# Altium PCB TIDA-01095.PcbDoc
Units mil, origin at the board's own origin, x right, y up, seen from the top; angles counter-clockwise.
Board outline 3070.87 x 3070.87 mil, 2 copper layers (Top Layer, Bottom Layer), stack 62 mil thick; 79 components, 37 nets, 208 pads, 92 vias.
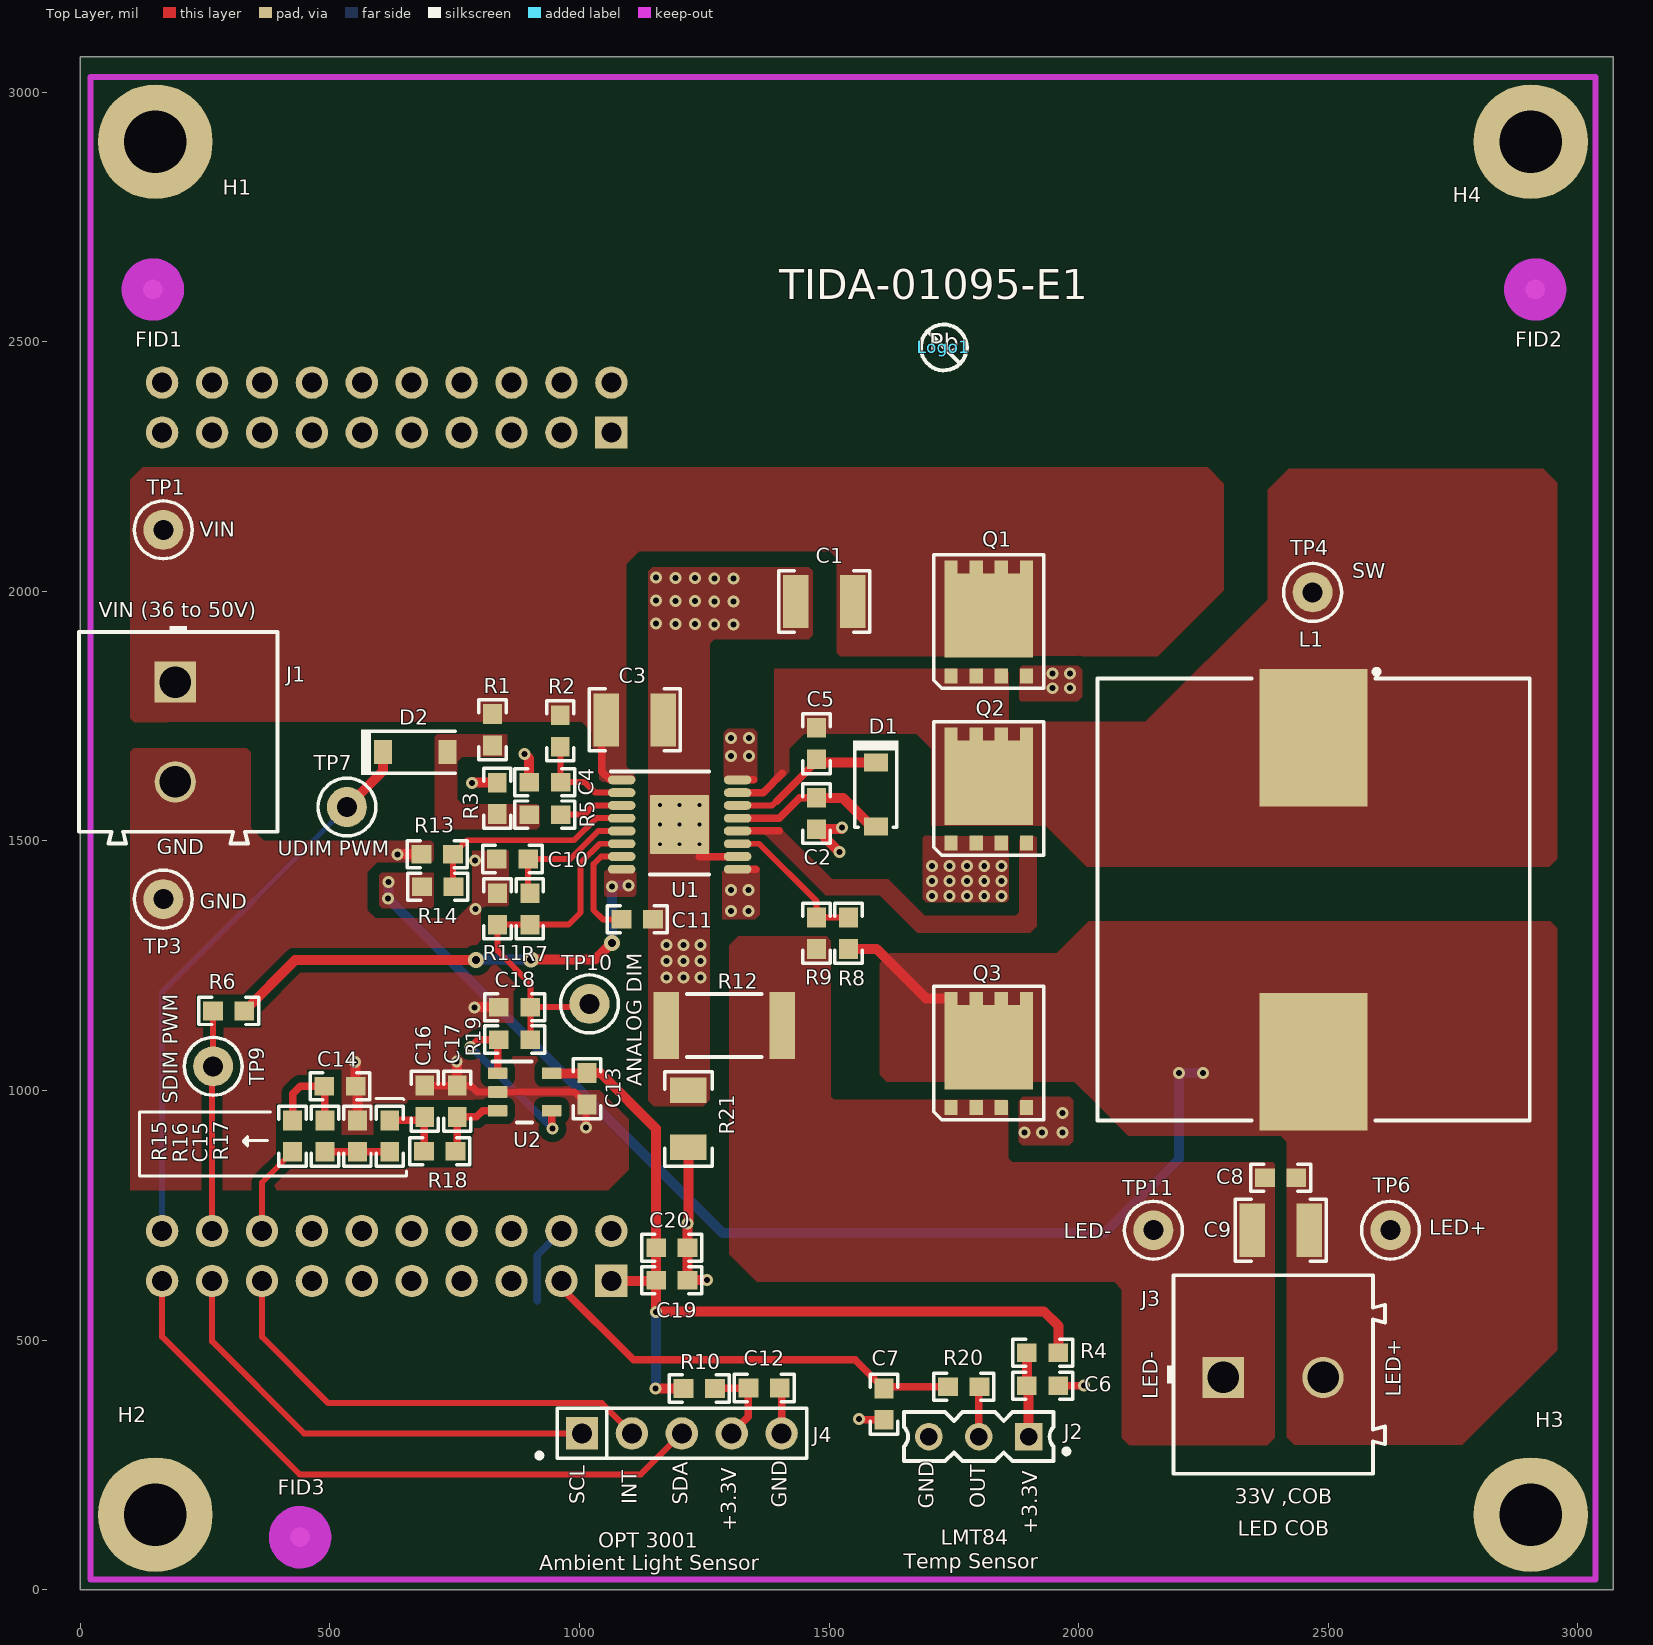
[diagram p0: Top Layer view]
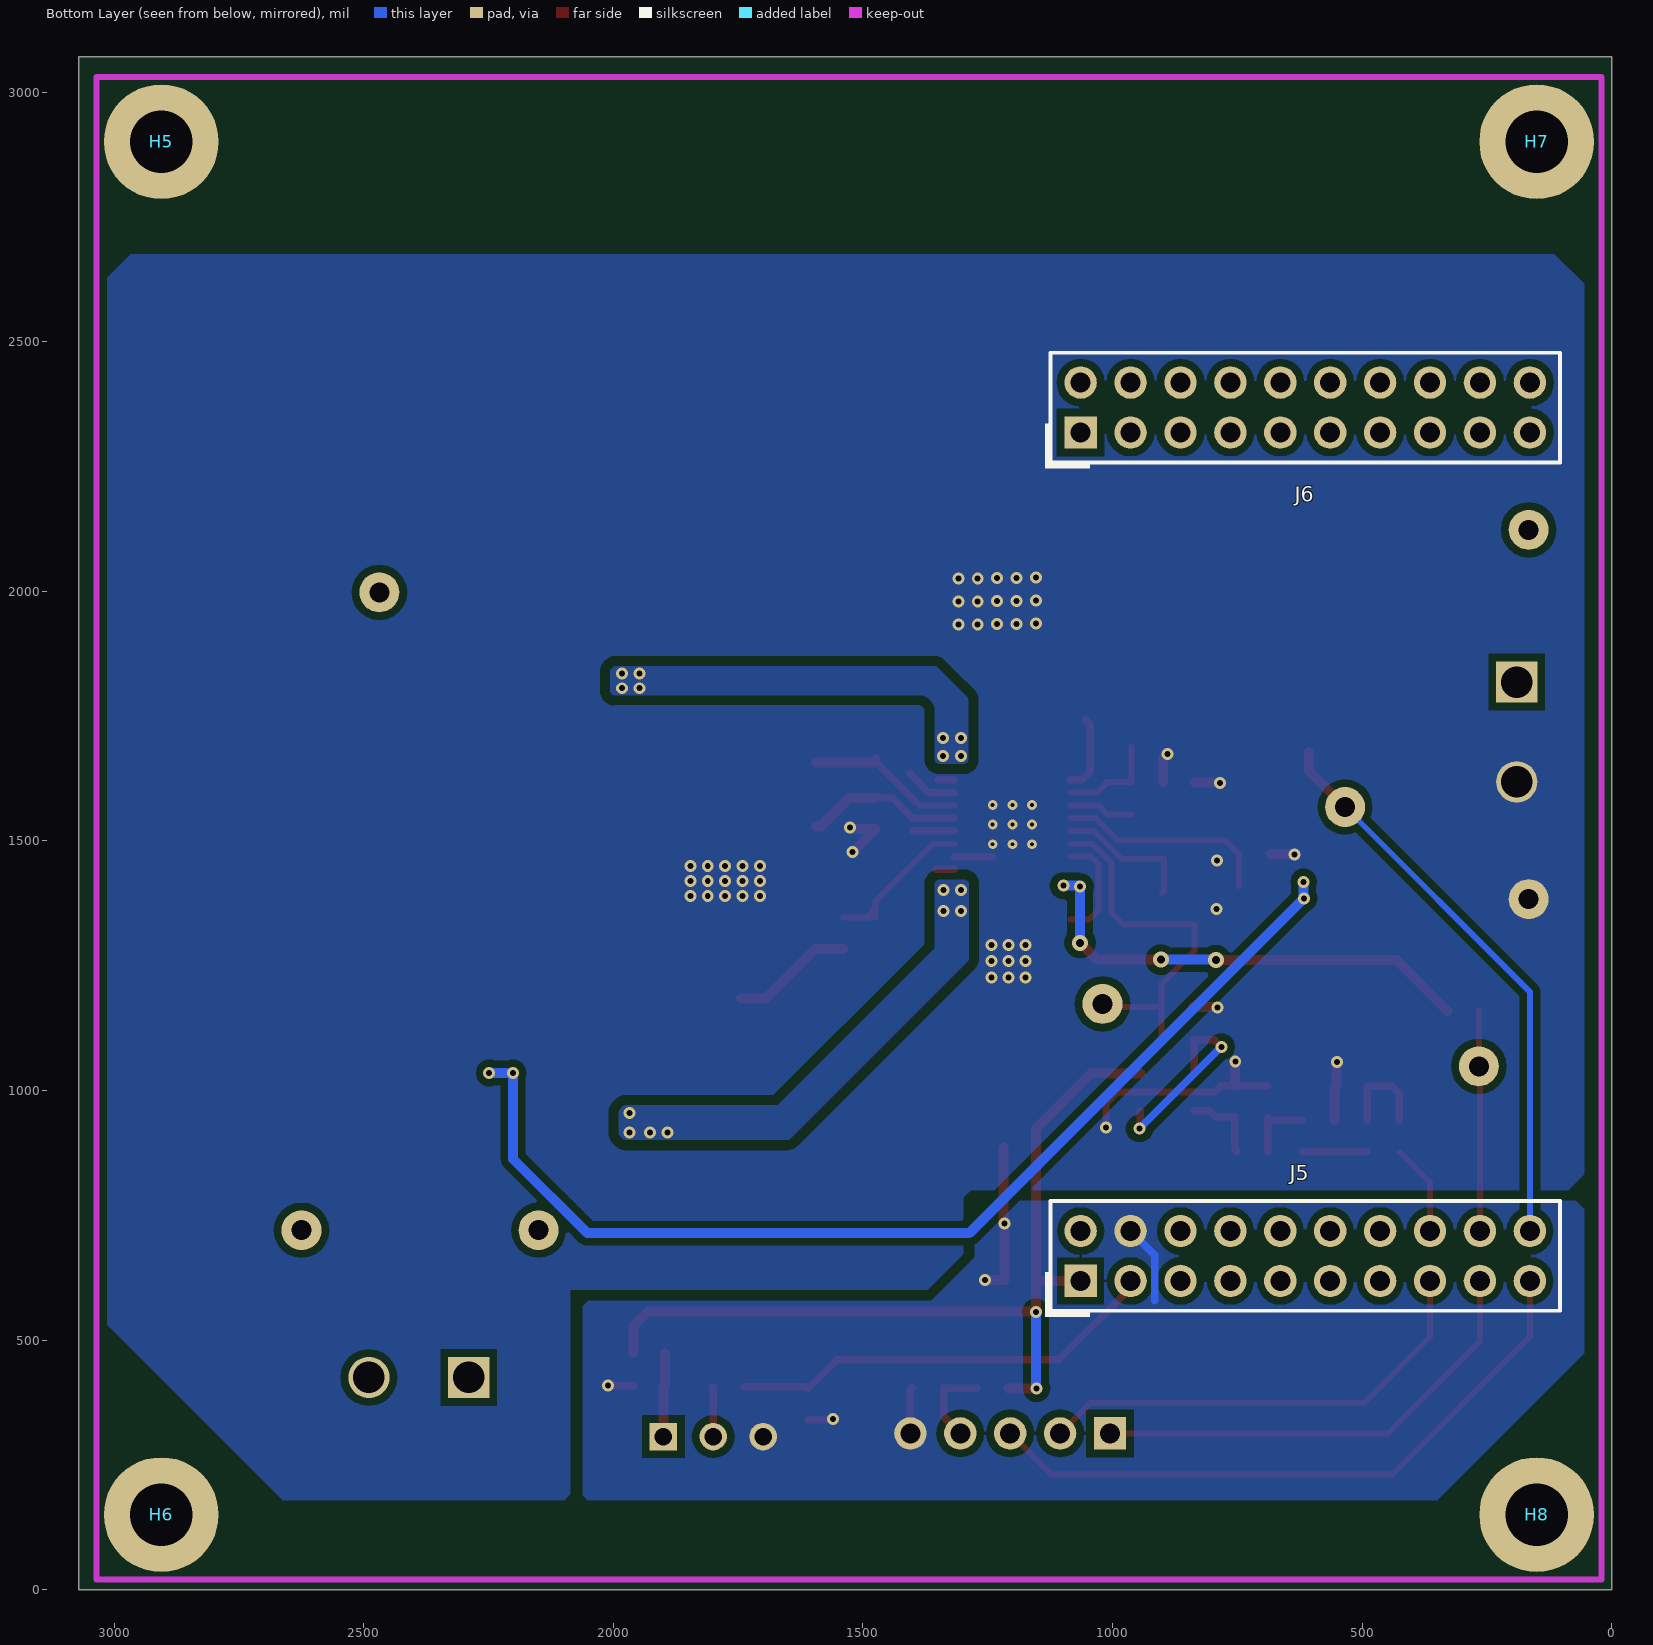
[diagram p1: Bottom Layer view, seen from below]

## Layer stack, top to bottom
Top Solder: solder mask 0.4, Solder Resist, Dk 3.5
Top Layer: signal copper 1.4
Dielectric1: core 59.2, FR-4, Dk 4.8
Bottom Layer: signal copper 1.4
Bottom Solder: solder mask 0.4, Solder Resist, Dk 3.5

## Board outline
0,0 3070.87,0 3070.87,3070.87 0,3070.87

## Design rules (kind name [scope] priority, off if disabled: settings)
AcuteAngle [All] p1: minimum=4.50000000000000E+0001 checktracksonly=FALSE
AssemblyTestPointUsage [All] p1: valid=2
Clearance Clearance_MTG_COPPER [InPadClass('MTG') vs InPoly] p1: gap=40
Clearance "Shape to Shape" [InPolygon vs InPolygon] p2: gap=20
Clearance "shape to all" [InPolygon] p3: gap=15
Clearance Clearance_Boardedge_poly [OnCopper and InPolygon vs IsKeepOut] p4: gap=20
Clearance "Clearance_via_thr pin" [IsVia vs IsThruPin] p5: gap=8
Clearance "SMD to Via" [IsSMTPin vs IsVia] p6: gap=8
Clearance Clearance_u [InPadClass('U1')] p7: gap=7.8
Clearance [All] p8: gap=8
DiffPairsRouting DiffPair_DiffPairsRouting [InDifferentialPair ('kan')] p1: maxlimit=10 minlimit=10 mostfreqgap=10 toplayer_minwidth=15 toplayer_maxwidth=15 toplayer_prefwidth=15 bottomlayer_minwidth=15 bottomlayer_maxwidth=15 bottomlayer_prefwidth=15 maxuncoupledlength=500
DiffPairsRouting DiffPair_DiffPairsRouting_1 [InDifferentialPair ('kan')] p2: maxlimit=10 minlimit=10 mostfreqgap=10 toplayer_minwidth=15 toplayer_maxwidth=15 toplayer_prefwidth=15 bottomlayer_minwidth=15 bottomlayer_maxwidth=15 bottomlayer_prefwidth=15 maxuncoupledlength=500
DiffPairsRouting [All] p3: maxlimit=100 minlimit=10 mostfreqgap=10 toplayer_minwidth=15 toplayer_maxwidth=15 toplayer_prefwidth=15 bottomlayer_minwidth=15 bottomlayer_maxwidth=15 bottomlayer_prefwidth=15 maxuncoupledlength=1000
FabricationTestPointUsage TestPointUsage [All] p1: valid=2 allowmultiple=FALSE
FabricationTestpoint Testpoint [All] p1: side=3 testpointundercomponent=TRUE minsize=40 maxsize=100 preferedsize=60 minholesize=0 maxholesize=40 preferedholesize=32 testpointgrid=1 allowsidetop=TRUE allowsidebottom=TRUE usegrid=TRUE gridtolerance=0.01
FanoutControl Fanout_LCC [IsLCC] p1: bgadir=Out bgaviamode=Centered fanoutstyle=Auto fanoutdirection=Alternating viagrid=1 // Fanout_LCC (Default Rule)
FanoutControl Fanout_BGA [IsBGA] p2: bgadir=Out bgaviamode=Centered fanoutstyle=Auto fanoutdirection=Alternating viagrid=1 // Fanout_BGA (Default Rule)
FanoutControl Fanout_Default [All] p4: bgadir=Out bgaviamode=Centered fanoutstyle=Auto fanoutdirection=Alternating viagrid=1 // Fanout_Default (Default Rule)
FanoutControl Fanout_Small [(CompPinCount < 5)] p5: bgadir=Out bgaviamode=Centered fanoutstyle=Auto fanoutdirection=OutThenIn viagrid=1 // Fanout_Small (Default Rule)
HoleSize [All] p1: absolutevalues=TRUE maxlimit=251 minlimit=7 maxpercent=80.000 minpercent=20.000
MatchedLengths DiffPair_MatchedLengths [InDifferentialPair ('kan')] p1: tolerance=1000 checknetsindiffpair=TRUE checkdiffpairvsdiffpair=FALSE checkothers=FALSE
MatchedLengths DiffPair_MatchedLengths_1 [InDifferentialPair ('kan')] p2: tolerance=1000 checknetsindiffpair=TRUE checkdiffpairvsdiffpair=FALSE checkothers=FALSE
MinimumAnnularRing [All] p1: minimumring=5
MinimumAnnularRing MinimumAnnularRing_ThermalPadVias [IsVia and InAnyComponent] p2: minimumring=5.91
MinimumSolderMaskSliver MinimumSolderMaskSliver_Logo [InComponentClass('Logo') vs InComponentClass('Logo')] p1: minsoldermaskwidth=0.7
MinimumSolderMaskSliver [All] p2: minsoldermaskwidth=3.94
PlaneClearance [All] p1: clearance=15
PlaneConnect [All] p1: planeconnectstyle=Direct reliefexpansion=10 reliefentries=4 reliefconductorwidth=10 reliefairgap=10
PolygonConnect [All] p1: connectstyle=Direct reliefconductorwidth=10 reliefentries=4 polygonreliefangle="90 Angle" airgapwidth=10
RoutingVias RoutingVias_power [InNetClass('POWER')] p1: holewidth=16 width=32 viastyle="Through Hole" minholewidth=7.87 minwidth=19.68 maxholewidth=16 maxwidth=32
RoutingVias ThermalPadVias [IsVia and InAnyComponent] p2: holewidth=8 width=20 viastyle="Through Hole" minholewidth=7.87 minwidth=19 maxholewidth=12 maxwidth=24
RoutingVias [All] p3: holewidth=12 width=24 viastyle="Through Hole" minholewidth=7.87 minwidth=19.68 maxholewidth=16 maxwidth=32
SMDToCorner [All] p1: distance=30000
SilkToSilkClearance [All] p1: silktosilkclearance=5
SilkToSolderMaskClearance SilkscreenOverComponentPads [IsPad] p1: minsilkscreentomaskgap=5 clearancetoexposedcopper=TRUE
SolderMaskExpansion [All] p1: expansion=3
UnpouredPolygon [All] p1: allowunpoured=FALSE
Width Width_power [InNetClass('pwr')] p1: maxlimit=200 minlimit=8 preferedwidth=20
Width [All] p2: maxlimit=100 minlimit=12 preferedwidth=12 checkconnectedcopper=TRUE
15 further rules are at their usual default settings.

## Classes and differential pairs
component class TIDA-01095_Sheet1: C1 C2 C3 C4 C5 C6 C7 C8 C9 C10 C11 C12 C13 C14 C15 C16 C17 C18 C19 C20 D1 D2 J1 J2 J3 J4 J5 J6 L1 Q1 Q2 Q3 R1 R2 R3 R4 R5 R6 R7 R8 R9 R10 R11 R12 R13 R14 R15 R16 R17 R18 R19 R20 R21 TP1 TP3 TP4 TP6 TP7 TP9 TP10 TP11 U1 U2
pad class MTG: H1-1 H2-1 H3-1 H4-1 H5-0 H6-0 H7-0 H8-0
component class Header: J2 J4 J5 J6
component class AssemblyNote: ZZ1 ZZ2 ZZ3 ZZ4
pad class U1: U1-1 U1-2 U1-3 U1-4 U1-5 U1-6 U1-7 U1-8 U1-9 U1-10 U1-11 U1-12 U1-13 U1-14 U1-15 U1-16 U1-17
component class TIDA-01095_Hardware: FID1 FID2 FID3 H1 H2 H3 H4 H5 H6 H7 H8 Logo1 ZZ1 ZZ2 ZZ3 ZZ4
component class FiducialMark: FID1 FID2 FID3

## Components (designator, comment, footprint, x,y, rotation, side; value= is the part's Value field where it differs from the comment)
C1 "GRM32ER72A225KA35L" 1210_270 1490,1980 r180 top
C2 "GRM188R61C225KE15D" 0603 1475,1555 r270 top
C3 "C3225X7R2A105K200AA" 1210 1110.63,1742.8 r0 top
C4 "GRM188R71E182KA01D" 0603 930.63,1617.8 r180 top
C5 "GRM188R71E224KA88D" 0603 1475,1695 r270 top
C6 "GRT188C81A106ME13D" 0603 1928,408.43 r0 top
C7 "GRM188R71E104KA01D" 0603 1610,371.43 r270 top
C8 "GRM188R71E104KA01D" 0603 2405,825 r180 top
C9 "GRM32RR71H105KA01L" 1210_200 2405,720 r180 top
C10 "GRM188R71E104KA01D" 0603 865.63,1463.8 r180 top
C11 "CGA3E3X7R1E474K080AB" 0603 1115.63,1342.8 r0 top
C12 "GRT188C81A106ME13D" 0603 1370,404 r0 top
C13 "GRM188R71E104KA01D" 0603 1015,1003.43 r270 top
C14 "GRM188R70J474KA01D" 0603 520,1008.43 r0 top
C15 "GRM188R70J473KA01D" 0603 555,908.43 r90 top
C16 "GCM188R71H472KA37D" 0603 690,978.43 r90 top
C17 "C0603X471K5RACTU" 0603 755,978.43 r90 top
C18 "GRM188R70J474KA01D" 0603 870,1166.97 r180 top
C19 "GRM188R71E104KA01D" 0603 1185,620 r0 top
C20 "GRT188C81A106ME13D" 0603 1185,685 r180 top
D1 "MBR1H100SFT3G" SOD-123FL 1594,1593 r270 top
D2 "1N4148W-7-F" SOD-123 670.63,1677.8 r0 top
FID1 "Fiducial" Fiducial10-30 145,2605 r0 top
FID2 "Fiducial" Fiducial10-30 2915,2605 r90 top
FID3 "Fiducial" Fiducial10-30 440,105 r90 top
H1 "PMSSS 440 0025 PH" B_F_PMSSS4400025PH 150,2901 r0 top
H2 "PMSSS 440 0025 PH" B_F_PMSSS4400025PH 150,150 r0 top
H3 "PMSSS 440 0025 PH" B_F_PMSSS4400025PH 2906,150 r0 top
H4 "PMSSS 440 0025 PH" B_F_PMSSS4400025PH 2906,2901 r0 top
H5 "1902E" Keystone_1902E 2906,2901 r180 bottom
H6 "1902E" Keystone_1902E 2906,150 r180 bottom
H7 "1902E" Keystone_1902E 150,2901 r180 bottom
H8 "1902E" Keystone_1902E 150,150 r180 bottom
J1 "691216510002" Wurth_691216510002 190,1718.43 r270 top
J2 "SL 11 112 03G" Fischer_SL-11-112-03G 1800,306.43 r180 top
J3 "691216510002" Wurth_691216510002 2390,425 r0 top
J4 "TSW-105-07-G-S" TSW-105-07-G-S 1205,313 r0 top
J5 "PEC10DAAN" SULLINS_PEC10DAAN 613.75,668.43 r90 bottom locked
J6 "PEC10DAAN" SULLINS_PEC10DAAN 613.75,2368.43 r90 bottom locked
L1 "68.0 μH" "WE-HCI 2212" 2471,1382.43 r0 top
Logo1 "Pb-Free Symbol" Pb-Free_Overlay_Small 1730,2489 r0 top
Q1 "CSD18537NQ5A" TRANS_NexFET_Q5A 1820,1940 r90 top
Q2 "CSD18563Q5A" TRANS_NexFET_Q5A 1820,1605 r90 top
Q3 "CSD18563Q5A" TRANS_NexFET_Q5A 1820,1075 r90 top
R1 "CRCW0603120KJNEA" 0603 825.63,1722.8 r90 top
R2 "CRCW060347K0JNEA" 0603 961.65,1720.6 r90 top
R3 "CRCW06034K99FKEA" 0603 835,1585.43 r270 top
R4 "RC0603FR-07100RL" 0603 1928,474.43 r0 top
R5 "CRCW060320K0FKEA" 0603 930.63,1552.8 r0 top
R6 "RC0603FR-07866RL" 0603 297,1159.43 r0 top
R7 "CRCW060310K0FKEA" 0603 900.63,1363.8 r90 top
R8 "CRCW06031M21FKEA" 0603 1539,1315 r270 top
R9 "CRCW0603475RFKEA" 0603 1475,1315 r270 top
R10 "RC0603FR-07100RL" 0603 1240,403 r0 top
R11 "CRCW060310K0FKEA" 0603 835.63,1363.8 r270 top
R12 "CSRN2512FK50L0" 2512 1290,1130 r0 top
R13 "CRCW06035K60JNEA" 0603 715,1473.43 r0 top
R14 "RC0603FR-07100KL" 0603 716,1408 r180 top
R15 "RC0603FR-07866RL" 0603 425,908.43 r90 top
R16 "RC0603FR-078K66L" 0603 490,908.43 r270 top
R17 "CRCW060386K6FKEA" 0603 620,908.43 r90 top
R18 "RC0603FR-07866KL" 0603 720,878.43 r0 top
R19 "CRCW060311K0FKEA" 0603 870,1101.97 r0 top
R20 "RC0603FR-071K5L" 0603 1770,406.43 r0 top
R21 "MCR18EZHJ000" 1206 1218,943 r90 top
TP1 "5002" Keystone5002 166,2123.43 r180 top
TP3 "5002" Keystone5002 166,1383.43 r0 top
TP4 "5002" Keystone5002 2469,1998 r0 top
TP6 "5002" Keystone5002 2625,720 r0 top
TP7 "5002" Keystone5002 534,1568 r90 top
TP9 "5002" Keystone5002 266,1048.43 r0 top
TP10 "5002" Keystone5002 1020,1173.43 r180 top
TP11 "5002" Keystone5002 2150,720 r0 top
U1 "TPS92641PWPR/NOPB" PWP0016A_N 1200.63,1532.8 r0 top
U2 "OPA376AIDBVR" DBV0005A_N 890,996.97 r0 top
ZZ1 "This Assembly Note is for PCB labels only" AssemblyNoteLabel 210.18,6697.51 r0 top
ZZ2 "These assemblies are ESD sensitive, ESD precautions shall be observed." AssemblyNote 1561.9,9244.61 r0 top
ZZ3 "These assemblies must be clean and free from flux and all contaminants. Use of no clean flux is not acceptable." AssemblyNote 1561.9,9159.61 r0 top
ZZ4 "These assemblies must comply with workmanship standards IPC-A-610 Class 2, unless otherwise specified." AssemblyNote 1561.9,9084.61 r0 top

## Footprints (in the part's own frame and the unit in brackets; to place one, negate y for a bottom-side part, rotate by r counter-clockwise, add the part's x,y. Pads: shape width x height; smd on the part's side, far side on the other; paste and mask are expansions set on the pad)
0603 [mm] "0603 from SM-752 data"
  rect 1x0.95 smd: 1(-0.8,0) 2(0.8,0)
  silkscreen extent -1.52,-0.69 1.52,0.69, body extent -0.87,-0.47 0.87,0.47, height 1
1206 [mm] "1206 from SM-752 data"
  rect 1.3x1.85 smd: 1(-1.45,0) 2(1.45,0)
  silkscreen extent -2.4,-1.21 2.4,1.21, body extent -1.7,-0.9 1.7,0.9, height 1.35
1210 [mm] "1210 from SM-752 data"
  rect 1.3x2.7 smd: 1(-1.45,0) 2(1.45,0)
  silkscreen extent -2.32,-1.57 2.32,1.57, body extent -1.7,-1.35 1.7,1.35, height 1.35
1210_200 [mm] "1210"
  rect 1.3x2.7 smd: 1(-1.45,0) 2(1.45,0)
  silkscreen extent -2.32,-1.57 2.32,1.57, body extent -1.7,-1.35 1.7,1.35, height 2
1210_270 [mm] "1210"
  rect 1.3x2.7 smd: 1(-1.45,0) 2(1.45,0)
  silkscreen extent -2.32,-1.57 2.32,1.57, body extent -1.7,-1.35 1.7,1.35, height 2.7
2512 [mm] "Chip Resistor, Body 6.3x3.2mm, IPC Medium Density"
  rect 1.3x3.4 smd: 1(-2.95,0) 2(2.95,0)
  silkscreen extent -1.9,-1.6 1.9,1.6, body extent -3.22,-1.67 3.22,1.67, height 0.71
AssemblyNote [mil] "Assembly Note"
AssemblyNoteLabel [mil] "Assembly Note for PCB Labels"
B_F_PMSSS4400025PH [mil] "MACHINE SCREW PAN PHILLIPS 4-40"
  round 230 hole 125: 1(0,0)
  body extent -109,-109 110,110, height 79
DBV0005A_N [mm] "SOT23, 5-Leads, Body 2.9x1.6mm, Pitch 0.95mm, Lead Span 2.8mm, IPC Medium Density"
  rrect17% 1x0.6 smd: 1(-1.375,0.95) 2(-1.375,0) 3(-1.375,-0.95) 4(1.375,-0.95) 5(1.375,0.95)
  silkscreen extent -1.63,-1.55 0.38,1.55, body extent -1.42,-1.46 1.42,1.46, height 1.09
Fiducial10-30 [mm]
  round 1 smd mask+1: 1(0,0)
  Top Layer keep-out circle w1.678: c0,0 r0.75
Fischer_SL-11-112-03G [mm] "TH, 3-Leads, Body 2.5x7.62mm, Pitch 2.54mm"
  rect 1.4x1.4 hole 0.9: 1(-2.54,0)
  round 1.4 hole 0.9: 2(0,0) 3(2.54,0)
  silkscreen extent -4.59,-1.25 3.81,1.25, body extent -3.81,-1.25 3.81,1.25, height 8.4
Keystone5002 [mil] "For Keystone 500x miniature loop terminals"
  round 80 hole 40: 1(0,0)
  silkscreen extent -58,-58 58,58, body extent -49,-49 49,49, height 182
Keystone_1902E [mil] "Hex Standoff, 4-40 threaded, nylon"
  round 1 on Mech4: 0(0,0)
  body extent -145,-126 146,126, height 1001
Pb-Free_Overlay_Small [mil]
  silkscreen extent -46,-46 46,46
PWP0016A_N [mm] "TSOP, 16-Leads, Body 5x4.4mm, Pitch 0.65mm, Exposed Pad, IPC Medium Density"
  rrect100% 1.4x0.45 smd: 1(-2.95,2.275) 2(-2.95,1.625) 3(-2.95,0.975) 4(-2.95,0.325) 5(-2.95,-0.325) 6(-2.95,-0.975) 7(-2.95,-1.625) 8(-2.95,-2.275) 9(2.95,-2.275) 10(2.95,-1.625) 11(2.95,-0.975) 12(2.95,-0.325) 13(2.95,0.325) 14(2.95,0.975) 15(2.95,1.625) 16(2.95,2.275)
  rrect3% 3x3 smd: 17(0,0)
  silkscreen extent -3.5,-2.55 1.5,2.7, body extent -3.21,-2.5 3.21,2.5, height 1
SOD-123 [mm] "On Semi recommended land pattern"
  rect 0.915x1.22 smd: 1(-1.637,0) 2(1.637,0)
  silkscreen extent -2.74,-1.17 2.03,1.17, body extent -1.93,-0.9 1.93,0.9, height 1.35
SOD-123FL [mm] "Copied from SOD-123"
  rect 0.915x1.22 smd: 1(-1.637,0) 2(1.637,0)
  silkscreen extent -2.74,-1.16 1.68,1.16, body extent -1.9,-0.9 1.9,0.9, height 1
SULLINS_PEC10DAAN [mm] "SULLINS"
  rect 1.65x1.65 hole 1.016: 1(-1.27,11.43)
  round 1.65 hole 1.016: 2(1.27,11.43) 3(-1.27,8.89) 4(1.27,8.89) 5(-1.27,6.35) 6(1.27,6.35) 7(-1.27,3.81) 8(1.27,3.81) 9(-1.27,1.27) 10(1.27,1.27) 11(-1.27,-1.27) 12(1.27,-1.27) 13(-1.27,-3.81) 14(1.27,-3.81) 15(-1.27,-6.35) 16(1.27,-6.35) 17(-1.27,-8.89) 18(1.27,-8.89) 19(-1.27,-11.43) 20(1.27,-11.43)
  silkscreen extent -3.11,-12.96 2.79,13.25, body extent -2.79,-12.96 2.79,12.96, height 9.08
TRANS_NexFET_Q5A [mm] "TI recommended land pattern (nominal) M0139-01"
  rect 0.75x0.675 smd paste-0.1 mask+0.051: 1(-2.776,1.917) 2(-2.776,0.639) 3(-2.776,-0.639) 4(-2.776,-1.917)
  rect 0.655x0.675 smd paste-0.1 mask+0.051: 5(2.776,-1.917) 6(2.776,-0.639) 7(2.776,0.639) 8(2.776,1.917)
  rect 4.295x4.51 smd paste-2.2 mask+0.051: 9(0.301,0)
  silkscreen extent -3.4,-2.8 3.4,2.8, body extent -3.05,-2.5 3.05,2.5, height 1.11
TSW-105-07-G-S [mm] "Samtec 100mil, 1x5, 230 mil above insulator"
  rect 1.65x1.65 hole 1.016 mask+0: 1(-5.08,0)
  round 1.65 hole 1.016 mask+0.076: 2(-2.54,0) 3(0,0) 4(2.54,0) 5(5.08,0)
  silkscreen extent -7.37,-1.27 6.35,1.27, body extent -6.35,-1.27 6.35,1.27, height 8.38
"WE-HCI 2212" [mm] "High Current Inductor, 2-Leads, Body 22.0x22.5mm"
  rect 5.5x7 smd: 1(0,8.25) 2(0,-8.25)
  silkscreen extent -11,-11.25 11,11.72, body extent -11,-11.25 11,11.25, height 12
Wurth_691216510002 [mm] "Receptacle, 5.08mm, 2x1, TH"
  rect 2.1x2.1 hole 1.6: 1(-2.54,0)
  round 2.1 hole 1.6: 2(2.54,0)
  silkscreen extent -5.4,-4.9 5.68,5.2, body extent -5.1,-4.9 5.66,5.2, height 13.8

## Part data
C1: "CAP, CERM, 2.2 µF, 100 V, +/- 10%, X7R, 1210"
C2: "CAP, CERM, 2.2 µF, 16 V, +/- 10%, X5R, 0603"
C3: "CAP, CERM, 1 µF, 100 V, +/- 10%, X7R, 1210"
C4: "CAP, CERM, 1800 pF, 25 V, +/- 10%, X7R, 0603"
C5: "CAP, CERM, 0.22 µF, 25 V, +/- 10%, X7R, 0603"
C6 C12 C20: "CAP, CERM, 10 µF, 10 V, +/- 20%, X6S, AEC-Q200 Grade 2, 0603"
C7 C8 C10 C13 C19: "CAP, CERM, 0.1 µF, 25 V, +/- 10%, X7R, 0603"
C9: "CAP, CERM, 1 µF, 50 V, +/- 10%, X7R, 1210"
C11: "CAP, CERM, 0.47 µF, 25 V, +/- 10%, X7R, AEC-Q200 Grade 1, 0603"
C14 C18: "CAP, CERM, 0.47 µF, 6.3 V, +/- 10%, X7R, 0603"
C15: "CAP, CERM, 0.047 µF, 6.3 V, +/- 10%, X7R, 0603"
C16: "CAP, CERM, 4700 pF, 50 V, +/- 10%, X7R, AEC-Q200 Grade 1, 0603"
C17: "CAP, CERM, 470 pF, 50 V, +/- 10%, X7R, 0603"
D1: "Diode, Schottky, 100 V, 1 A, SOD-123FL"
D2: "Diode, Ultrafast, 100 V, 0.15 A, SOD-123"
FID1 FID2 FID3: "Fiducial mark.  There is nothing to buy or mount."
H1 H2 H3 H4: "MACHINE SCREW PAN PHILLIPS 4-40"
H5 H6 H7 H8: "Standoff, Hex, 1\"L #4-40 Nylon"
J1 J3: "Receptacle, 5.08mm, 2x1, Brass, TH"
J2: "Header, 2.54mm, 3x1, Gold, TH"
J4: "Header, 100mil, 5x1, Gold, TH"
J5 J6: "Header, 100mil, 10x2, TH"
L1: library part "WE-HCI 2212, 74435586800", "WE-HCI SMD Flat Wire High Current Inductor, Inductance = 68.0 µH"
Logo1: library part Pb-Free
Q1: "MOSFET, N-CH, 60 V, 50 A, SON 5x6mm"
Q2 Q3: "MOSFET, N-CH, 60 V, 15 A, SON 5x6mm"
R1: "RES, 120 k, 5%, 0.1 W, 0603"
R2: "RES, 47 k, 5%, 0.1 W, 0603"
R3: "RES, 4.99 k, 1%, 0.1 W, 0603"
R4 R10: "RES, 100, 1%, 0.1 W, 0603"
R5: "RES, 20.0 k, 1%, 0.1 W, 0603"
R6 R15: "RES, 866, 1%, 0.1 W, 0603"
R7 R11: "RES, 10.0 k, 1%, 0.1 W, 0603"
R8: "RES, 1.21 M, 1%, 0.1 W, 0603"
R9: "RES, 475, 1%, 0.1 W, 0603"
R12: "RES, 0.05, 1%, 2 W, 2512"
R13: "RES, 5.6 k, 5%, 0.1 W, 0603"
R14: "RES, 100 k, 1%, 0.1 W, 0603"
R16: "RES, 8.66 k, 1%, 0.1 W, 0603"
R17: "RES, 86.6 k, 1%, 0.1 W, 0603"
R18: "RES, 866 k, 1%, 0.1 W, 0603"
R19: "RES, 11.0 k, 1%, 0.1 W, 0603"
R20: "RES, 1.50 k, 1%, 0.1 W, 0603"
R21: "RES, 0, 5%, 0.25 W, 1206"
TP1 TP3 TP4 TP6 TP7 TP9 TP10 TP11: "Test Point, Miniature, White, TH"
U1: "Synchronous Buck Controller for Precision Dimming LED Drivers, PWP0016A"
U2: "Precision, Low Noise, Low Iq Operational Amplifier, 2.2 to 5.5 V, -40 to 125 degC, 5-pin SOT23 (DBV0005A), Green (RoHS & no Sb/Br)"
ZZ1: library part AssemblyNoteLabel
ZZ2 ZZ3 ZZ4: library part AssemblyNote

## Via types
v1: diameter 24, hole 12, Top Layer to Bottom Layer, tented both sides, 80 vias
v2: diameter 19.68, hole 7.87, Top Layer to Bottom Layer, tented both sides, 9 vias
v3: diameter 32, hole 16, Top Layer to Bottom Layer, tented both sides, 3 vias

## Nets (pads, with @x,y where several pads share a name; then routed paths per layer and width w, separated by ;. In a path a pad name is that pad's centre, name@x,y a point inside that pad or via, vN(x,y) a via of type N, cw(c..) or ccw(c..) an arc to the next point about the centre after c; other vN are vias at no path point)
+3.3V: C13.1 C19.1 C20.2 J5.1 R4.2 R10.1 U2.5 | length 1795.2
  Top Layer w20: U2.5 1014.45,1034.37 C13.1 1042.08,1034.92 1153.5,923.5 C19.1 ; J5.1 1151.93,618.43 C19.1 ; v1(1152,403) R10.1 ; v1(1153.5,556.5) C19.1 ; v1@1154.01,557 1931,557 1959.5,528.5 R4.2
  Bottom Layer w20: v1(1152,403) 1153.5,404.5 v1(1153.5,556.5)
+5V: J5.2
DIO0: J5.18 R6.1 TP9.1 | length 442.1
  Top Layer w12: J5.18 263.75,1046.17 TP9.1 266,1158.93 R6.1
DIO1: D2.1 J5.20 TP7.1 | length 1142.6
  Top Layer w20: TP7.1 606.16,1640.16 D2.1
  Bottom Layer w12: J5.20 163.75,1197.75 TP7.1
DIO4_SCL: J4.1 J5.17 | length 938.7
  Top Layer w12: J5.17 263.75,497.25 448,313 J4.1
DIO5_SDA: J4.3 J5.19 | length 1301.4
  Top Layer w12: J5.19 163.75,506.25 439,231 1123,231 J4.3
DIO21: J4.2 J5.15 | length 933.5
  Top Layer w12: J5.15 363.75,506.25 496.57,373.43 1044.57,373.43 J4.2
DIO30: J5.16 R15.1 | length 183.9
  Top Layer w12: J5.16 363.75,815.68 R15.1
GND: C1.2 C2.2 C3.2 C4.2 C10.2 C11.2 C13.2 C14.2 C15.2 C16.2 C17.2 C18.2 J1.2 Q2.1 Q2.2 Q2.3 R3.1 R11.1 R12.1 R13.1 R21.2 TP3.1 U1.10 U1.17 U2.2 | length 956.5
  Top Layer w15: C16.2 C17.2 782.05,1009.92 795,996.97 U2.2 989.96,996.97 C13.2 1013,969.93 v1(1013,925.43) ; 1240.4,1468.82 U1.10
  Top Layer w20: v1(550.5,1056.93) 551.5,1055.93 C14.2 555,1004.92 C15.2 ; v1(635,1472.43) 636,1473.43 R13.1 ; v1(754,1058.43) 755,1057.42 C17.2 ; v1(785.01,1616.43) 785.5,1616.92 R3.1 ; v1(790,1165.97) 791,1166.97 C18.2 ; v1(890,1674.43) 899.14,1665.29 C4.2 ; v1(1521,1478) 1520.5,1478 C2.2 v1@1522.5,1523.5 ; v1@1526,1523.5 v1(1526,1527)
  other v1: 1174,1226 1208,1226 1242,1226 1174,1259 1208,1259 1242,1259 1174,1292 1208,1292 1242,1292 792,1364 1706,1390 1741,1390 1776,1390 1811,1390 1846,1390 1706,1420 1741,1420 1776,1420 1811,1420 1846,1420 1706,1450 1741,1450 1776,1450 1811,1450 1846,1450 791,1461 1309,1933.72 1192,1935 1231,1934.57 1270,1934.15 1153,1935.43 1309,1979.72 1192,1981 1231,1980.57 1270,1980.15 1153,1981.43 1309,2025.72 1192,2027 1231,2026.57 1270,2026.15 1153,2027.43
  other v2: 1161.26,1493.43 1200.63,1493.43 1240,1493.43 1161.26,1532.8 1200.63,1532.8 1240,1532.8 1161.26,1572.17 1200.63,1572.17 1240,1572.17
GND1: C6.2 C7.2 C12.2 C19.2 C20.1 J2.3 J4.5 J5.4 R21.1 | length 659.8
  Top Layer w15: C12.2 1405,400.5 J4.5 ; v1(1560,341.43) 1561.5,339.93 C7.2 ; C6.2 v1(2011,408.43)
  Top Layer w20: R21.1 1218,735.01 v1(1216.5,733.5) C20.1 C19.2 v1(1255,620)
  Bottom Layer w15: 915,578.43 915,669.68 J5.4
NetC1_1: C1.1 C3.1 J1.1 Q1.5 Q1.6 Q1.7 Q1.8 Q1.9 R1.2 R2.2 TP1.1 U1.1 | length 154.1
  Top Layer w15: C3.1 1045,1734.25 1045,1638.43 1061.06,1622.36 U1.1
NetC2_1: C2.1 D1.2 U1.13 | length 318.2
  Top Layer w15: U1.13 1400.53,1545.59 1441.43,1586.5 C2.1
  Top Layer w20: C2.1 1527.5,1586.5 1585.47,1528.53 D1.2
NetC4_1: C4.1 R2.1 U1.2 | length 202.6
  Top Layer w12: R2.1 961.65,1618.28 C4.1 1010.63,1617.8 1031.65,1596.77 U1.2
NetC5_1: C5.1 L1.1 Q1.1 Q1.2 Q1.3 Q2.5 Q2.6 Q2.7 Q2.8 Q2.9 TP4.1 U1.15 | length 105.7
  Top Layer w15: U1.15 1367.79,1596.77 1406.48,1635.46
NetC5_2: C5.2 D1.1 U1.14 | length 320
  Top Layer w12: U1.14 1386.18,1571.18 1395,1580
  Top Layer w15: 1395,1580 C5.2@1475,1660
  Top Layer w20: C5.2@1475,1660 C5.2@1478.5,1660 ; C5.2 C5.2@1478.5,1660 ; D1.1 1481.04,1657.47 C5.2@1478.5,1660
NetC6_1: C6.1 J2.1 R4.1 | length 169.4
  Top Layer w20: R4.1 C6.1 1900,404.93 J2.1
NetC8_1: C8.1 C9.1 J3.2 L1.2 Q3.5 Q3.6 Q3.7 Q3.8 Q3.9 R8.2 R14.2 TP6.1 | length 2424.7
  Top Layer w20: R8.2 1595.5,1283.5 1694.7,1184.3 Q3.8
  Bottom Layer w20: v1(617,1418) 617,1386 v1(616,1385) 1287,714 2052,714 2201,863 v1(2201,1035) v1(2249,1035)
NetC8_2: C8.2 C9.2 J3.1 Q3.1 Q3.2 Q3.3 R9.2 R12.2 TP11.1
NetC10_1: C10.1 R7.2 U1.5 | length 280.6
  Top Layer w12: R7.2 897.13,1398.8 C10.1 981.37,1463.8 1037.58,1520 U1.5
NetC11_1: C11.1 U1.7 | length 218.7
  Top Layer w12: C11.1 1046.63,1342.8 1028,1361.43 1028,1453.43 1043.4,1468.82 U1.7
NetC12_1: C12.1 J4.4 R10.2 | length 172.3
  Top Layer w15: R10.2 1337.5,403 C12.1 1338.5,346.5 J4.4
NetC14_1: C14.1 R15.2 R16.1 | length 192.3
  Top Layer w15: R15.2 425,993.43 440,1008.43 C14.1 490,1006.93 R16.1
NetC15_1: C15.1 R16.2 R17.1 | length 130
  Top Layer w15: R16.2 C15.1 R17.1
NetC16_1: C16.1 R17.2 R18.1 | length 137.8
  Top Layer w15: R17.2 682.99,939.92 688.51,945.43 R18.1
NetC17_1: C17.1 R18.2 U2.3 | length 156.1
  Top Layer w15: R18.2 755,881.93 C17.1 793.51,946.93 806.14,959.57 U2.3
NetC18_1: C18.1 R7.1 R11.2 R19.2 TP10.1 U1.6 | length 753.2
  Top Layer w12: R19.2 C18.1 ; TP10.1 1013.55,1166.97 C18.1 ; U1.6 1040.27,1494.41 1002,1456.14 1002,1356.43 977.88,1332.3 R7.1 R11.2 835.63,1279.79 901.5,1213.93 C18.1
NetD2_2: D2.2 R1.1 R3.2 R5.1
NetJ2_2: J2.2 R20.2 | length 105.6
  Top Layer w15: J2.2@1796.5,309.93 J2.2 1800,404.93 R20.2
NetQ1_4: Q1.4 U1.16 | length 32.2
  Top Layer w15: U1.16 1349,1622.36
  other v1: 1304,1670.43 1340,1670.43 1304,1706.43 1340,1706.43 1948,1806 1983,1806 1948,1836 1983,1836
NetQ2_4: Q2.4 U1.12 | length 83.8
  Top Layer w15: U1.12 1400.53,1520
NetQ3_4: Q3.4 U1.9 | length 36.3
  Top Layer w15: U1.9 1316.97,1443.43 1353,1443.43
  other v1: 1892,916 1927,916 1968,916 1968,955 1304,1359.43 1339,1359.43 1304,1401.43 1339,1401.43
NetR5_2: R5.2 U1.3 | length 130
  Top Layer w12: R5.2 1009.37,1552.8 1027.76,1571.18 U1.3
NetR6_2: R6.2 U1.8 | length 936.5
  Top Layer w20: R6.2 430.07,1261 v3(793,1261) ; v3(903,1262) 1031,1262 v3(1065,1296)
  Bottom Layer w20: v3(793,1261) 794,1262 v3(903,1262) ; v3(1065,1296) v1(1065,1408.43) ; v1@1067,1410.43 v1(1098,1410.43)
NetR8_1: R8.1 R9.1 U1.11 | length 323.7
  Top Layer w12: U1.11 1359.59,1494.41 1475,1379 R9.1@1475,1365 ; R9.1@1490,1350 R9.1@1475,1365 ; R8.1 R9.1 R9.1@1475,1365
NetR13_2: R13.2 R14.1 U1.4 | length 431.9
  Top Layer w12: R14.1@746.5,1409.43 R13.2 774.5,1501.43 989,1501.43 1033.17,1545.59 U1.4
NetR19_1: R19.1 U2.1 U2.4 | length 400.2
  Top Layer w12: R19.1@835.87,1099.33 R19.1 ; v1@944.14,925.56 944,925.43 v1(946,923.43)
  Top Layer w15: v1(782,1087.43) 796.55,1101.97 R19.1 ; U2.1 R19.1@835.87,1099.33 ; v1@944.14,925.56 U2.4
  Bottom Layer w15: v1(782,1087.43) v1(946,923.43)
TEMP_1: C7.1 J5.3 R20.1 | length 873.5
  Top Layer w15: J5.3 963.75,604.68 1108.43,460 1552.92,460 C7.1 1613.5,406.43 R20.1
pads on no net: FID1.1 FID2.1 FID3.1 H1.1 H2.1 H3.1 H4.1 H5.0 H6.0 H7.0 H8.0 J5.5 J5.6 J5.7 J5.8 J5.9 J5.10 J5.11 J5.12 J5.13 J5.14 J6.1 J6.2 J6.3 J6.4 J6.5 J6.6 J6.7 J6.8 J6.9 J6.10 J6.11 J6.12 J6.13 J6.14 J6.15 J6.16 J6.17 J6.18 J6.19 J6.20

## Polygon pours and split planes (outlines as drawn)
NetQ3_4 on Top Layer "Top Layer-No Net 6" (solid, remove dead copper, pour order 40): 1879.81,978.81 1879.81,897.19 1887,890 1981,890 1989,898 1989,980 1981.98,987.02 1888.02,987.02
NetC1_1 on Top Layer "Top Layer-No Net" (solid, remove dead copper, pour order 44): 1080,2050 1080,2248.43 2258.58,2248.42 2291,2216 2291,2002 2159,1870 1515,1870 1515,2066 1501,2080 1107,2080 1088.54,2061.54
NetC1_1 on Top Layer "Top Layer-No Net 1" (solid, remove dead copper, pour order 43): 1095,2068 1095,2233.43 1080,2248.43 125,2248.43 100,2223.43 100,1746 108,1738 174,1738 178,1742 178,1772 178,1824 178,1866 345,2033 860.43,2033 1060,2033
NetQ2_4 on Top Layer "Top Layer-No Net 16" (solid, remove dead copper, pour order 30): 1286.61,1524.92 1286.61,1516.26 1294.87,1508 1373,1508 1490,1391 1602,1391 1677,1316 1903,1316 1916,1329 1916,1507 1912,1511 1881,1511 1881,1357 1874,1350 1692,1350 1619,1423 1506,1423 1398,1531 1290.61,1531 1286.61,1527
GND on Top Layer "Top Layer-No Net 15" (solid, remove dead copper, pour order 27): 83879.08,1510 1860,1512 1860,1382 1855,1377 1695,1377 1688,1384 1688,1506 1692,1510
NetC5_1 on Top Layer "Top Layer-No Net 8" (solid, remove dead copper, pour order 24): 2592,2246 2931,2246 2959,2218 2959,1464 2943,1448 2016,1448 1934,1530 1705,1530 1705,1685 1675,1715 1450,1715 1420,1685 1420,1638 1390.02,1608.02 1390.02,1845 1730,1845 1860,1845 1860,1738.86 2134.08,1738.86 2379,1983.78 2379,2204 2421,2246
GND on Top Layer "Top Layer-No Net 17" (solid, remove dead copper, pour order 46): 813,1484.43 856,1484.43 858,1482.43 858,1372.43 855,1369.43 811.09,1369.43 807.09,1365.43 807.09,1275.34 819,1263.43 1087,1263.43 1099,1251.43 1099,841.43 1058,800.43 100,800.43 100,1679 106.42,1685.42 333,1685.43 341,1677.43 341,1526.43 355,1512.43 367,1500.43 696,1500.43 703,1500.43 708,1495.43 708,1461.57 703.43,1457 594.57,1457 575,1437.43 575,1361.43 591.43,1345 754,1345 785,1376 785,1484.43
NetQ3_4 on Top Layer "Top Layer-No Net 11" (solid, remove dead copper, pour order 45): 1301,1455.43 1357,1455.43 1361,1451.42 1361,1345.42 1358.57,1343 1286,1343 1286,1450.43 1291,1455.43
GND on Top Layer "Top Layer-No Net 9" (solid, remove dead copper, pour order 42): 1138,1481.43 1138,2043.43 1143,2048.43 1460.58,2048.43 1467,2042 1467,1912 1459.43,1904.43 1270,1904.43 1261,1895.43 1261,981 1248,968 1149,968 1138,979 1138,1480.43
NetQ1_4 on Top Layer "Top Layer-No Net 7" (solid, remove dead copper, pour order 41): 1299,1610.43 1355.92,1610.42 1356.1,1717.9 1349.01,1725 1297,1725 1289,1717 1289,1610.43
NetC8_1 on Top Layer "Top Layer-No Net 5" (solid, remove dead copper, pour order 38): 655.02,1436.63 706.8,1436.63 708,1435.43 708,1369.43 704,1365.43 605,1365.43 599,1371.43 599,1431.43 604,1436.43
NetR6_2 on Top Layer "Top Layer-No Net 4" (solid, remove dead copper, pour order 35): 1054,1454.43 1107.11,1454.43 1113.38,1448.15 1113.38,1392.81 1109,1388.43 1053,1388.43 1050,1391.43 1050,1451.43 1053,1454.43
NetD2_2 on Top Layer "Top Layer-No Net 3" (solid, remove dead copper, pour order 32): 854.17,1713.43 715,1713.43 710,1708.43 710,1528.43 715,1523.43 914.17,1523.43 919.17,1528.43 919.17,1569.25 915,1573.43 765,1573.43 755,1583.43 755,1658.43 765,1668.43 850,1668.43 855,1673.43 855,1712.6 854.17,1713.43
NetD2_2 on Top Layer "Top Layer-No Net 2" (solid, remove dead copper, pour order 31): 805,1573.43 915,1573.43 920,1568.43 920,1529.25 915,1524.25 744.17,1524.25 740,1528.43 740,1568.43 745,1573.43
NetC1_1 on Top Layer "M2 Board Dimensions-No Net" (solid, remove dead copper, pour order 29): 1113.38,1613.43 1050,1613.43 1040,1623.43 1040,1673.43 1025,1688.43 1025,1717.86 1019.43,1723.43 1004.43,1738.43 197.57,1738.43 194,1742 194,1860 352.42,2018.42 1063.58,2018.42 1094,1988 1094,1650.1 1105,1639.1 1113.38,1630.71 1113.38,1627.29
NetQ1_4 on Top Layer "Top Layer-No Net" (solid, pour order 26): 1881,1842 1881,1780 1998,1780 2007,1789 2007,1843 1999,1851 1887,1851 1881,1845
NetC8_1 on Top Layer "Top Layer-No Net" (solid, pour order 33): 2417,801 2417,897 2405,909 2100,909 2042,967 1991,1018 1616,1018 1602,1032 1602,1255 1622,1275 1956,1275 2020,1339 2945,1339 2959,1325 2959,480 2769,290 2432,290 2417,305
NetC8_2 on Top Layer "Top Layer-No Net" (solid, pour order 36): 1495,1309 1318,1309 1300,1291 1300,672 1355,617 2071,617 2087,601 2087,304 2102,289 2378,289 2393,304 2393,852 2389,856 1867,856 1860,863 1859,864 1859,965 1859,979 1857,981 1510,981 1503.54,987.46 1503.54,1300.46
NetC1_1 on Top Layer "Top Layer-No Net" (solid, remove dead copper, pour order 25): 197.57,1738.43 107.57,1738.43 100,1746 100,2223.43 125,2248.43 2258.57,2248.43 2291,2216 2291,2002 2159,1870 1522.07,1870 1515,1877.07 1515,2066 1501,2080 1120,2080 1097,2057 1094,2054 1094,1983 1094,1646.67 1113.38,1627.29 1113.38,1612.38 1111,1610 1053.43,1610 1040.09,1623.34 1040.09,1673.34 1025,1688.43 1025,1717.86 1004.43,1738.43 197.57,1738.43
NetQ1_4 on Bottom Layer "Top Layer-No Net" (solid, remove dead copper, pour order 28): 2006,1843 2006,1797 2001,1792 1382,1792 1356,1766 1356,1660 1351,1655 1294,1655 1289,1660 1289,1786 1353,1850 1999,1850
NetQ3_4 on Bottom Layer "Top Layer-No Net" (solid, pour order 39): 1979,901 1648,901 1288,1261 1288,1417.49 1292.51,1422 1351,1422 1356,1417 1356,1285 1671,970 1979,970 1989,960 1989,911
GND on Bottom Layer "Top Layer-No Net" (solid, remove dead copper, pour order 34): 55,2616 55,832 85,802 87,800 141,800 1160,800 1284,800 1299,785 1299,672 1370,601 1395,601 2087,601 2087,191 2099,179 2663.02,179 3020,535.98 3020,2623 2967,2676 783,2676 115,2676
GND1 on Bottom Layer "Top Layer-No Net" (solid, remove dead copper, pour order 37): 1185,779 85,779 72,779 60,767 55,762 55,705 55,473 349,179 2051,179 2061,189 2061,568 2050,579 1363,579 1286,656 1276,666 1276,758 1276,773 1270,779

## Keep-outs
Keep-Out Layer:
  lines w12: 20,20 20,3031 3036,3031 3036,20 20,20
  text ".Layer_Name" at -265.1,-1454.89 h60

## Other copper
Top Layer:
  text ".layer_Name" at -250.1,-1444.39 h60
Bottom Layer:
  text ".Layer_Name" at -191.1,-1454.39 h60

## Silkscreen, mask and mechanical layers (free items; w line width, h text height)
Top Overlay:
  lines w6: 327,897 335,889 335,908 327,900 375,900 ; 381,957 118,957 118,829 653,829 653,839 ; 592,984 646,984 648.54,981.46
  text "TIDA-01095-E1" at 1400,2585 h60
  text "VIN" at 239,2110 h30
  text "SW" at 2548,2026 h30
  text "VIN (36 to 50V)" at 37,1948 h30
  text "GND" at 153,1473 h30
  text "UDIM PWM" at 395,1470 h30
  text "GND" at 239,1364 h30
  text "ANALOG DIM" at 1125,1008 h30 r90
  text "SDIM PWM" at 195,973 h30 r90
  text "LED+" at 2703,711 h30
  text "LED-" at 1970,704 h30
  text "LED+" at 2646,386 h30 r90
  text "LED-" at 2159,381 h30 r90
  text "33V ,COB" at 2313,172 h30
  text "SCL" at 1010,171 h30 r90
  text "INT" at 1115,171 h30 r90
  text "SDA" at 1217,170 h30 r90
  text "GND" at 1415,164 h30 r90
  text "OUT" at 1813,163 h30 r90
  text "GND" at 1710,162 h30 r90
  text "+3.3V" at 1314,117 h30 r90
  text "+3.3V" at 1917,111 h30 r90
  text "LED COB" at 2319,108 h30
  text "LMT84" at 1724,90 h30
  text "OPT 3001" at 1038,84 h30
  text "Temp Sensor" at 1650,42 h30
  text "Ambient Light Sensor" at 919,39 h30
  text ".layer_Name" at -224.1,-1442.39 h60
Bottom Overlay:
  text ".Layer_Name" at -265.1,-1454.89 h60
Top Paste:
  text ".Layer_Name" at -277.1,-1457.89 h60
Bottom Paste:
  text ".Layer_Name" at -277.1,-1457.89 h60
Top Solder:
  text ".Layer_Name" at -249.1,-1465.39 h60
Bottom Solder:
  text ".Layer_Name" at -202.1,-1461.39 h60
M1 Board Outline:
  the board outline again, w12
M2 Board Dimensions:
  rectangle: -247.6,-601.39 127.4,-476.39
  lines w6: -372.6,-351.39 377.4,-351.39 627.4,-351.39
  lines w7: -372.6,-351.39 -372.6,-601.39 627.4,-601.39 627.4,-351.39 ; -247.6,-601.39 -247.6,-351.39 ; -122.6,-601.39 -122.6,-351.39 ; 127.4,-601.39 127.4,-351.39 ; 377.4,-601.39 377.4,-351.39
  lines w10: -372.6,-666.39 -372.6,-646.39 ; -312.6,-676.39 -372.6,-656.39 ; -312.6,-636.39 -372.6,-656.39 ; -148.52,-656.39 -372.6,-656.39 ; 403.32,-656.39 627.4,-656.39 ; 567.4,-676.39 627.4,-656.39 ; 567.4,-636.39 627.4,-656.39 ; 627.4,-666.39 627.4,-646.39
  text "1000 (mil)" at -138.52,-692.38 h60
M3 3D STEP Top:
  text ".Layer_Name" at -265.1,-1454.89 h60
M4 3D STEP Bottom:
  lines w10: 103.71,753.58 103.71,558.58 1129.71,558.58 1129.71,750.58 106.71,750.58 ; 105.71,2451.58 105.71,2256.58 1131.71,2256.58 1131.71,2448.58 108.71,2448.58
  lines w11.81: -683.69,361.58 -683.69,2684.42 3056.46,2684.42 3056.46,361.58 -683.69,361.58
  text ".Layer_Name" at -265.1,-1454.89 h60
M5 Assembly Top:
  circle w10: c188,1819 r25.08
  circle w10: c816,1035 r8.25
  circle w10: c2288,422 r26.25
  circle w10: c1898,307 r15
  circle w10: c2477,1706 r26.08
  lines w10: 2349.51,940 2041,940 2041,1826 2352,1826 ; 2600,1825.34 2911,1825.34 2911,939.34 2602.49,939.34
  lines w12: -1134.1,-1526.56 5465.9,-1526.56 ; -1134.1,-1323.23 5467.9,-1323.23 ; -1134.1,-1119.89 -1134.1,-1729.89 2870.9,-1729.89 5467.9,-1729.89 5467.9,-1119.89 -1133.6,-1119.89 -1133.6,-1729.89 ; 1330.9,-1729.89 1330.9,-1119.89 ; 2597.9,-1323.23 2597.9,-1119.89 ; 3437.9,-1323.23 3437.9,-1119.89 ; 4059.9,-1736.39 4059.9,-1533.56
  text "L1" at 2447,1364 h30
  text "COMPONENTS MARKED 'DNP' SHOULD NOT BE POPULATED." at 311.4,-914.89 h30
  text "ASSEMBLY VARIANT:" at 310.9,-1030.39 h30
  text ".VariantName" at 1346.9,-1030.39 h30
  text "ALL ARTWORK VIEWED FROM TOP SIDE" at -1070.6,-1252.06 h30
  text "BOARD #:" at 1405.9,-1252.06 h30
  text ".PRJ_Number" at 1951.4,-1252.06 h30
  text "REV:" at 2795.9,-1252.06 h30
  text ".PCB_Rev" at 3087.4,-1252.06 h30
  text "SVN REV:" at 3633.9,-1252.06 h30
  text ".VersionControl_RevNumber" at 4139.9,-1252.06 h30
  text ".layer_Name" at -307.1,-1434.39 h30
  text "LAYER NAME =" at -1077.1,-1441.39 h30
  text "TID #:" at 1410.9,-1452.06 h30
  text ".PRJ_Number" at 1781.4,-1452.06 h30
  text ".plot_File_Name" at -1079.1,-1630.39 h30
  text "GENERATED    :" at 1407.9,-1660.73 h30
  text ".Print_Date" at 2277.4,-1660.73 h30
  text ".Print_Time" at 3006.4,-1660.73 h30
  text "TEXAS INSTRUMENTS" at 4270.9,-1660.73 h30
M6 Assembly Bottom:
  lines w6: -1134.6,-1323.73 5467.4,-1323.73 ; -1132.6,-1527.06 5467.4,-1527.06 ; 895.4,-1323.73 895.4,-1120.39 ; 1735.4,-1323.73 1735.4,-1120.39 ; 3002.4,-1730.39 3002.4,-1120.39 ; 3891.4,-1730.39 5466.9,-1730.39 5466.9,-1120.39 -1134.6,-1120.39 -1134.6,-1730.39 1462.4,-1730.39 5467.4,-1730.39 5467.4,-1120.39
  text "COMPONENTS MARKED 'DNP' SHOULD NOT BE POPULATED." at 5259.9,-914.39 h30
  text ".VariantName" at 4215.9,-1030.39 h30
  text "ASSEMBLY VARIANT:" at 5254.9,-1030.39 h30
  text "SVN REV:" at 699.4,-1252.56 h30
  text ".PCB_Rev" at 1245.9,-1252.56 h30
  text "REV:" at 1537.4,-1252.56 h30
  text ".PRJ_Number" at 2381.9,-1252.56 h30
  text "BOARD #:" at 2927.4,-1252.56 h30
  text "PCB VIEWED FROM BOTTOM SIDE" at 5403.9,-1252.56 h30
  text "LAYER NAME =" at 5398.9,-1437.39 h30
  text ".Layer_Name" at 4625.9,-1444.39 h30
  text ".PRJ_Number" at 2378.6,-1447.06 h30
  text "TID #:" at 2904.1,-1452.06 h30
  text "IGNORE ->" at 1705.75,-1454.89 h30
  text ".Print_Time" at 1326.9,-1661.23 h30
  text ".Print_Date" at 2055.9,-1661.23 h30
  text "GENERATED    :" at 2925.4,-1661.23 h30
  text ".plot_File_Name" at 4598.4,-1661.23 h30
  text "PLOT NAME =" at 5403.9,-1661.23 h30
M9 Title Sheet:
  drawing of 57 lines, arcs and shapes, not listed
  text "1" at -102.26,7440.11 h70
  text "2" at 2393.4,7440.11 h70
  text "3" at 4882.74,7440.11 h70
  text "4" at 7389.41,7440.11 h70
  text "5" at 9888.4,7440.11 h70
  text "6" at 12393.4,7440.11 h70
  text "A" at -1258.6,6297.11 h70
  text "A" at 13541.4,6297.11 h70
  text "B" at -1258.6,3917.11 h70
  text "B" at 13541.4,3917.11 h70
  text "C" at -1258.6,1542.11 h70
  text "C" at 13541.4,1542.11 h70
  text "PROJECT TITLE:" at 10501.4,-318.89 h45
  text ".PRJ_Title" at 10564.18,-452.49 h70
  text "DESIGNED FOR:" at 10501.4,-619.89 h45
  text ".PRJ_Customer" at 10551.4,-759.89 h70
  text "D" at -1258.6,-827.89 h70
  text "D" at 13541.4,-827.89 h70
  text "FILE NAME:" at 10501.4,-919.89 h45
  text ".PCB_File_Name_No_Path" at 10832.9,-1045.39 h70
  text "Texas Instruments (TI) and/or its licensors do not warrant the accuracy or completeness of this specification" at 5531.9,-1201.73 h45
  text "ENGINEER:" at 10501.4,-1209.89 h45
  text "LAYOUT BY:" at 12006.4,-1209.89 h45
  text "or any information contained therein. TI and/or its licensors do not warrant that this design will meet" at 5486.91,-1314.4 h45
  text ".PRJ_Engineer" at 10551.4,-1364.88 h50
  text ".PCB_Layout" at 12056.9,-1364.88 h70
  text "the specifications, will be suitable for your application or fit for any particular purpose, or will operate in" at 5486.91,-1427.06 h45
  text "ALTIUM DESIGNER VERSION:" at 12006.4,-1519.89 h45
  text "an implementation. TI and/or its licensors do not warrant that the design is production worthy. You should" at 5486.91,-1539.73 h45
  text "completely validate and test your design implementation to confirm the system functionality for your application." at 5531.9,-1652.39 h45
  text ".print_Scale" at 10551.4,-1653.22 h70
  text ".Application_BuildNumber" at 12056.9,-1653.22 h70
  text "2" at 2393.4,-1859.89 h70
  text "3" at 4882.74,-1859.89 h70
  text "4" at 7389.41,-1859.89 h70
  text "5" at 9888.4,-1859.89 h70
  text "6" at 12393.4,-1859.89 h70
M10 Fab Notes:
  drawing of 228 lines, arcs and shapes, not listed
  text "DESIGN INFORMATION" at 11538.92,6213.61 h60
  text "(REFER ALSO ARRAY/PANEL PROFILING INFORMATION)" at 11177.36,6051.89 h60
  text "BOARD SIZE" at 10491.36,6047.61 h60
  text "78MM" at 10953.68,5919.79 h60
  text "X" at 11459.36,5919.79 h60
  text "78MM" at 11690.68,5919.79 h60
  text "Number of Layers :" at 10894.36,5722.61 h60
  text "2" at 11989.17,5712.61 h60
  text "MIN. TRACK WIDTH:" at 10894.36,5583.61 h60
  text "12" at 11990.6,5583.61 h60
  text "MIL" at 12145.36,5583.61 h60
  text "7.8" at 11949,5468.43 h60
  text "MIN. CLEARANCE:" at 10894.36,5451.61 h60
  text "MIL" at 12145.36,5451.61 h60
  text "7.874" at 11844,5321 h60
  text "MIN. VIA DRILL SIZE:" at 10894.36,5319.61 h60
  text "MIL" at 12145.36,5319.61 h60
  text "5.9055 MIL" at 11589.36,5177.9 h60
  text "MINIMUM ANNULAR RING" at 10565.13,5173.61 h60
  text "EXTERNAL" at 12297.36,5173.61 h60
  text "PER" at 10765.13,5055.61 h60
  text "IPC-D-275 CLASS 2 LEVEL C" at 10985.13,5055.61 h60
  text "MIL, HOLES" at 12473.36,4943.32 h60
  text "+/-" at 12080.9,4942.61 h60
  text "+/-" at 12934.9,4942.61 h60
  text "REGISTRATION TOLERANCES:" at 10565.13,4937.61 h60
  text "METAL" at 11764.9,4937.61 h60
  text "5" at 12341.1,4937.61 h60
  text "3" at 13174.1,4937.61 h60
  text "MIL" at 13290.36,4937.61 h60
  text "MATERIAL:" at 10490.36,4728.15 h60
  text "FR-4 High Tg" at 11476.8,4587.82 h60
  text "FR-408" at 10911.36,4579.25 h60
  text "X" at 11317.9,4579.61 h60
  text "OTHER" at 12399.36,4579.25 h60
  text "63 MIL (1.6mm) +/-10%" at 11231.46,4416.53 h60
  text "THICKNESS:" at 10565.13,4412.25 h60
  text "X" at 11103.3,4412.25 h60
  text "OTHER" at 12516.36,4412.25 h60
  text "TOLERANCE:" at 10565.13,4254.25 h60
  text "X" at 11404.43,4254.25 h60
  text "ANSI IPC-6012 TYPE 3 CLASS 2" at 11591.38,4254.25 h60
  text "OTHER +/-" at 11591.36,4098.25 h60
  text "BOW & TWIST:" at 10565.13,3941.25 h60
  text "X" at 11404.43,3941.25 h60
  text "ANSI IPC-6012 TYPE 3 CLASS 2" at 11591.38,3941.25 h60
  text "OTHER +/-" at 11591.36,3782.74 h60
  text "COPPER THICKNESS (FINISHED):" at 10490.36,3647.25 h60
  text "1.4MIL (1oz)" at 11370.36,3494.53 h60
  text "2MIL (1.4oz)" at 12137.36,3494.53 h60
  text "2.8MIL (2oz)" at 12864.36,3494.53 h60
  text "OUTER:" at 10847.36,3490.25 h60
  text "X" at 11241.9,3489.61 h60
  text "1.4MIL (1oz)" at 11370.36,3337.53 h60
  text "2.8MIL (2oz)" at 12137.36,3337.53 h60
  text "N/A" at 12863.9,3337.89 h60
  text "INNER SIGNAL:" at 10558.28,3333.25 h60
  text "DRILLING:" at 10490.36,3194.25 h60
  text "REFERENCE:" at 10565.13,3077.25 h60
  text "X" at 11213.36,3077.25 h60
  text "AS SHOWN" at 11400.36,3077.25 h60
  text "X" at 12114.36,3077.25 h60
  text "NC_DRILL FILES" at 12251.36,3077.25 h60
  text "PTH MIN COPPER THICKNESS:" at 10565.13,2919.25 h60
  text "X" at 11915.36,2919.25 h60
  text "1MIL" at 12052.36,2919.25 h60
  text "OTHER" at 12549.36,2919.25 h60
  text "BOARD FINISH:" at 10490.36,2760.25 h60
  text "SILKSCREEN:" at 10645.58,2642.25 h60
  text "X" at 11594.36,2642.25 h60
  text "TOP" at 11720.36,2642.25 h60
  text "X" at 12104.36,2642.25 h60
  text "BOTTOM" at 12231.36,2642.25 h60
  text "SILKSCREEN COLOR:" at 10645.58,2475.25 h60
  text "X" at 11593.32,2475.25 h60
  text "WHITE" at 11720.36,2475.25 h60
  text "OTHER" at 12231.36,2475.25 h60
  text "SOLDER RESIST COLOR:" at 10645.58,2305.25 h60
  text "X" at 11213.32,2146.05 h60
  text "GREEN" at 11340.36,2146.05 h60
  text "BLUE" at 11931.36,2146.05 h60
  text "OTHER" at 12469.36,2146.05 h60
  text "IMMERSION GOLD (ENIG)" at 11551.36,1957.53 h60
  text "ENEPIG" at 12888.9,1954.25 h60
  text "SURFACE FINISH:" at 10490.36,1953.25 h60
  text "X" at 11364.41,1953.25 h60
  text "IMM. TIN/SILVER OR EQUIV" at 10819.9,1796.25 h60
  text "OTHER" at 12251.36,1796.25 h60
  text "ARRAY/PANEL:" at 10490.36,1617.25 h60
  text "CUT AND TRIM PER MECH LAYER 1" at 11551.36,1612.96 h60
  text "N.C. ROUTE" at 11551.36,1461.25 h60
  text "X" at 12230.36,1461.25 h60
  text "V. SCORE" at 12417.36,1461.25 h60
  text "CERTIFICATION:" at 10490.36,1324.25 h60
  text "MATERIALS AND WORKMANSHIP FOR ALL PCBS" at 11215.36,1324.25 h60
  text "TO MEET OR EXCEED THE REQUIREMENTS OF:" at 11215.36,1226.25 h60
  text "X" at 10841.86,1089.74 h60
  text "ANSI IPC-A-600F CLASS ->" at 10980.86,1089.74 h60
  text "X" at 12619.92,1089.74 h60
  text "2" at 12738.86,1089.74 h60
  text "1" at 12423.86,1088.25 h60
  text "3" at 13092.86,1088.25 h60
  text "X" at 10843.92,930.25 h60
  text "UL 94V-0" at 10980.86,930.25 h60
  text "X" at 11655.92,930.25 h60
  text "RoHS" at 11792.86,930.25 h60
  text "OTHER" at 12437.26,930.25 h60
  text "PER ORDER" at 12834.32,930.25 h60
  text "X" at 12466,803 h60
  text "VIA TENTING:" at 11707.9,796.61 h60
  text "ADDITIONAL REQUIREMENTS:" at 10490.36,789.25 h60
  text "YES" at 12257.57,787.53 h60
  text "NO" at 12622.37,782.3 h60
  text "MICROSECTION:" at 10565.13,674.25 h60
  text "YES" at 11470.86,674.25 h60
  text "IMPEDANCE CONTROL:" at 11729.9,667.61 h60
  text "YES" at 12713.9,666.61 h60
  text "X" at 13255.9,659.61 h60
  text "NO" at 13089.37,649.3 h60
  text "REQUIRED" at 12332.36,518.1 h60
  text "BARE BOARD ELEC. TEST:" at 10565.13,515.25 h60
  text "NONE" at 11870.86,515.25 h60
  text "X" at 12205.36,515.25 h60
  text "PER ORDER" at 12924.36,515.25 h60
  text "MANUFACTURER'S UL:" at 10565.13,358.25 h60
  text "RAIL" at 11730.86,353.96 h60
  text "METAL" at 12222.67,353.96 h60
  text "X" at 12597.9,353.61 h60
  text "SILK" at 12734.36,353.96 h60
M11 Gerber Information:
  lines w12: -1134.1,-1526.56 5465.9,-1526.56 ; -1134.1,-1323.23 5467.9,-1323.23 ; -1134.1,-1119.89 -1134.1,-1729.89 2870.9,-1729.89 5467.9,-1729.89 5467.9,-1119.89 -1133.6,-1119.89 -1133.6,-1729.89 ; 1330.9,-1729.89 1330.9,-1119.89 ; 2597.9,-1323.23 2597.9,-1119.89 ; 3437.9,-1323.23 3437.9,-1119.89 ; 4059.9,-1736.39 4059.9,-1533.56
  text ".PRJ_Number" at 1886.18,-1246.49 h40
  text "BOARD #:" at 1405.9,-1252.06 h60
  text "REV:" at 2795.9,-1252.06 h60
  text ".PCB_Rev" at 3087.4,-1252.06 h60
  text "SVN REV:" at 3633.9,-1252.06 h60
  text ".VersionControl_RevNumber" at 4139.9,-1252.06 h60
  text "ALL ARTWORK VIEWED FROM TOP SIDE" at -1071.6,-1258.06 h60
  text "LAYER NAME =" at -1073.1,-1441.39 h60
  text ".PRJ_Number" at 1766.18,-1456.49 h40
  text "TID #:" at 1400.9,-1462.06 h60
  text ".plot_File_Name" at -1081.1,-1640.39 h60
  text "GENERATED    :" at 1407.9,-1660.73 h60
  text ".Print_Date" at 2277.4,-1660.73 h60
  text ".Print_Time" at 3006.4,-1660.73 h60
  text "TEXAS INSTRUMENTS" at 4270.9,-1660.73 h60
M12 Stackup:
  lines w6: 10517.9,6863.61 13067.9,6863.61 ; 10517.9,6968.01 13067.9,6968.01 ; 10457.9,6378.61 ccw(c10491.9,6378.61) 10491.9,6344.61 13093.9,6344.61 ccw(c13093.9,6378.61) 13127.9,6378.61 13127.9,7084.61 ccw(c13093.9,7084.61) 13093.9,7118.61 10491.9,7118.61 ccw(c10491.9,7084.61) 10457.9,7084.61 10457.9,6378.61
  text "Layer Stack Up Detail for: TIDA-01095-E1" at 10476.18,6974.51 h57
  text "Layer" at 10517.9,6929.01 h24
  text "Gerber" at 11413.71,6929.01 h24
  text "Copper" at 11977.23,6929.01 h24
  text "Dielectric" at 12579.94,6929.01 h24
  text "Name" at 10517.9,6881.01 h24
  text "Document" at 11413.71,6881.01 h24
  text "Thickness" at 11977.23,6881.01 h24
  text "Material" at 12579.94,6881.01 h24
  text "Top Solder Mask" at 10532.9,6789.61 h34
  text "(.GTS)" at 11413.71,6788.05 h34
  text "Solder Resist" at 12579.94,6788.05 h34
  text "Top Layer" at 10527.9,6694.61 h34
  text "(.GTL)" at 11413.71,6691.3 h34
  text "1.4mil" at 11977.23,6691.3 h34
  text "FR4-High Tg" at 12608.9,6690.61 h34
  text "FR4-High Tg" at 12613.9,6465.61 h34
  text "Bottom Layer" at 10522.9,6464.61 h34
  text "(.GBL)" at 11421.9,6460.61 h34
  text "1.4mil" at 11981.9,6454.61 h34
  text "Solder Resist" at 12573.9,6387.61 h34
  text "(.GBS)" at 11418.9,6380.61 h34
  text "Bottom Solder Mask" at 10527.9,6379.61 h34
M13 Component Bodies Top:
  text ".Layer_Name" at -265.1,-1454.89 h60
M14 Component Bodies Bottom:
  text ".Layer_Name" at -265.1,-1454.89 h60
M15 Courtyards Top:
  text ".Layer_Name" at -265.1,-1454.89 h60
M16 Courtyards Bottom:
  text ".Layer_Name" at -265.1,-1454.89 h60
Drill Drawing:
  text ".legend" at 4324.9,1231.61 h60
  text "Drill Table" at 4321.9,1060.61 h60
  text "FOR 7.874MIL DRILL +0/-7.874MIL" at 4321.9,896.61 h60
  text "FOR 12MIL DRILL +0/-12MIL" at 4321.9,791.61 h60
  text "FOR PTH DRILL +/-3MIL" at 4328.18,685.51 h60
  text ".layer_Name" at -160.1,-1438.39 h60

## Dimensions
0,0 to 3070.87,0 on M2 Board Dimensions
3070.87,3070.87 to 3070.87,0 on M2 Board Dimensions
